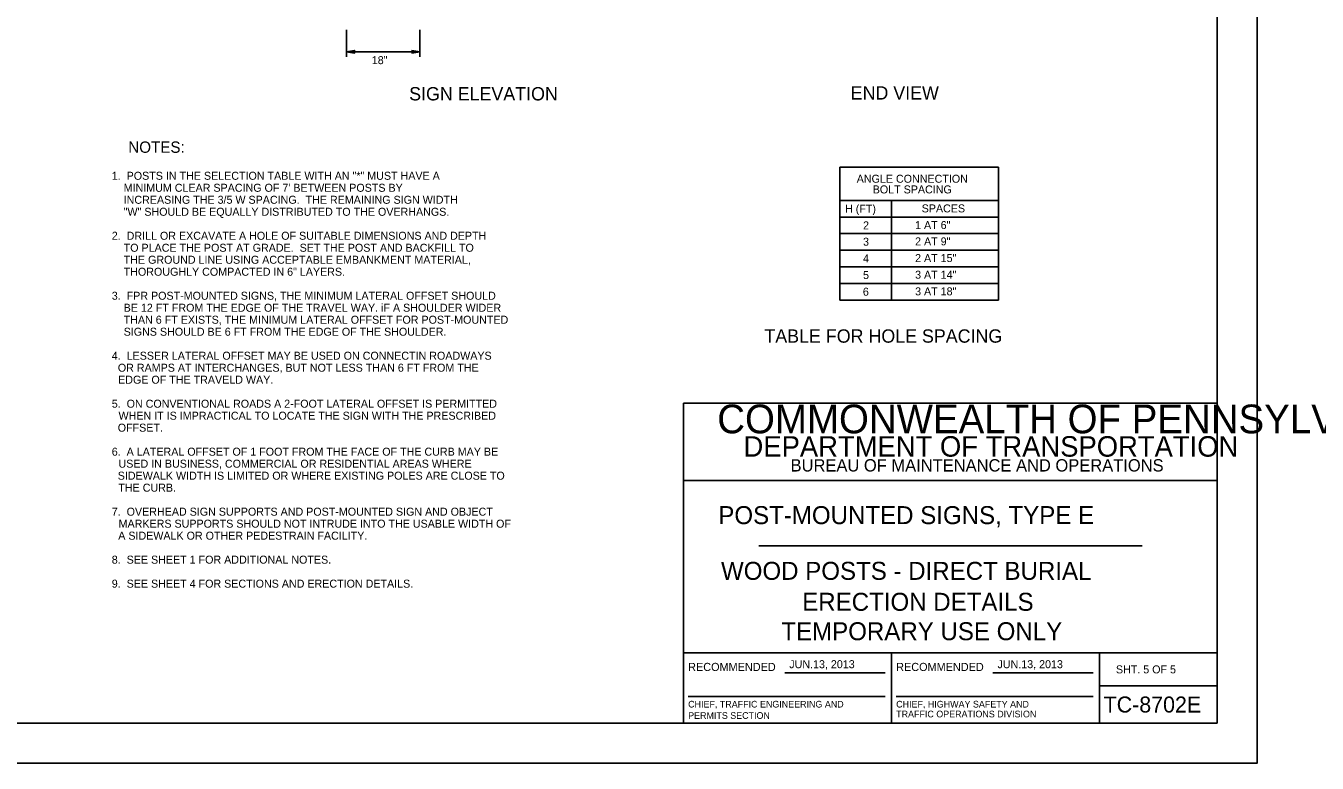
# Model space of a CAD drawing. Extents: x -2340 to 628, y -879 to 309.
# Drawn here: x -738 to -253.8, y -878.6 to -602 of the extents above; entities that cross this region are included whole.
import ezdxf

# ---------------------------------------------------------------- set-up
doc = ezdxf.new("R2010")
doc.units = 0
for name, color, linetype in [('Level 1', 7, 'Continuous'), ('Level 2', 7, 'Continuous'), ('Level 3', 7, 'Continuous'), ('Level 4', 7, 'Continuous'), ('PLT-BNDY', 7, 'Continuous')]:
    doc.layers.add(name, color=color, linetype=linetype)

msp = doc.modelspace()

# ---------------------------------------------------------------- linework, layer by layer
at = {"layer": 'Level 1'}
for p, q in [((-291.39, -863.56), (-291.39, -299.56)), ((-491.39, -863.56), (-491.39, -743.56)), ((-491.39, -743.56), (-291.39, -743.56)), ((-291.39, -772.56), (-491.39, -772.56)), ((-463.14, -797.06), (-319.51, -797.06)), ((-491.39, -837.19), (-291.39, -837.19)), ((-413.39, -837.19), (-413.39, -863.56)), ((-335.51, -863.56), (-335.51, -837.19)), ((-453.45, -844.62), (-415.83, -844.62)), ((-375.45, -844.62), (-337.83, -844.62)), ((-335.51, -849.56), (-291.39, -849.56)), ((-489.7, -853.51), (-415.83, -853.51)), ((-411.7, -853.51), (-337.83, -853.51)), ((-291.39, -863.56), (-1077.39, -863.56)), ((-1077.39, -863.56), (-491.39, -863.56))]:
    msp.add_line(p, q, dxfattribs=at)
at = {"layer": 'Level 2'}
for p, q in [((-373.31, -654.95), (-432.81, -654.95)), ((-432.81, -704.83), (-432.81, -654.95)), ((-373.31, -704.83), (-373.31, -654.95)), ((-373.31, -667.45), (-432.81, -667.45)), ((-413.42, -704.83), (-413.42, -667.45)), ((-373.31, -673.7), (-432.81, -673.7)), ((-373.31, -679.83), (-432.81, -679.83)), ((-373.31, -686.08), (-432.81, -686.08)), ((-373.31, -692.33), (-432.81, -692.33)), ((-373.31, -698.58), (-432.81, -698.58)), ((-373.31, -704.83), (-432.81, -704.83))]:
    msp.add_line(p, q, dxfattribs=at)
at = {"layer": 'Level 3'}
for p, q in [((-617.78, -613.59), (-617.78, -603.47)), ((-590.28, -613.59), (-590.28, -603.47)), ((-617.78, -611.72), (-590.28, -611.72))]:
    msp.add_line(p, q, dxfattribs=at)
for points in [[(-614.78, -612.09), (-614.9, -611.84), (-617.78, -611.72), (-614.78, -612.09), (-614.78, -612.22), (-617.78, -611.72), (-614.9, -611.59), (-614.78, -611.34), (-617.78, -611.72), (-614.78, -611.22), (-614.78, -611.34)], [(-593.15, -611.34), (-593.03, -611.59), (-590.28, -611.72), (-593.15, -611.34), (-593.28, -611.22), (-590.28, -611.72), (-593.03, -611.84), (-593.15, -612.09), (-590.28, -611.72), (-593.28, -612.22), (-593.15, -612.09)]]:
    msp.add_lwpolyline(points, dxfattribs=at)
at = {"layer": 'PLT-BNDY'}
msp.add_lwpolyline([(-1117.39, -284.56), (-276.39, -284.56), (-276.39, -878.56), (-1117.39, -878.56)], close=True, dxfattribs=at)

# ---------------------------------------------------------------- texts
at = {"layer": 'Level 1'}
for s, height, p in [('COMMONWEALTH OF PENNSYLVANIA', 10.7827, (-478.79, -754.83)), ('DEPARTMENT OF TRANSPORTATION', 7.6838, (-468.93, -763.58)), ('BUREAU OF MAINTENANCE AND OPERATIONS', 4.6252, (-451.29, -769.15)), ('POST-MOUNTED SIGNS, TYPE E', 6.7492, (-478.39, -788.89)), ('WOOD POSTS - DIRECT BURIAL', 6.7492, (-477.38, -809.79)), ('ERECTION DETAILS ', 6.7492, (-446.93, -821.4)), ('TEMPORARY USE ONLY', 6.7492, (-454.76, -832.44)), ('RECOMMENDED', 3.048, (-489.7, -843.99)), ('RECOMMENDED', 3.048, (-411.7, -843.99)), ('SHT. 5 OF 5', 3, (-329.3, -844.88)), ('CHIEF, TRAFFIC ENGINEERING AND', 2.5, (-489.7, -857.68)), ('CHIEF, HIGHWAY SAFETY AND', 2.5, (-411.7, -857.68)), ('TC-8702E', 6, (-333.91, -859.56)), ('PERMITS SECTION', 2.5, (-489.7, -861.93)), ('TRAFFIC OPERATIONS DIVISION', 2.5, (-411.7, -861.38))]:
    msp.add_text(s, height=height, dxfattribs=at).set_placement(p)
at = {"layer": 'Level 2'}
for p in [(-451.78, -842.93), (-373.71, -842.93)]:
    msp.add_text('JUN.13, 2013', height=3, dxfattribs=at).set_placement(p)
at = {"layer": 'Level 3'}
for s, height, p in [('18"', 3, (-608.32, -616.35)), ('SIGN ELEVATION', 5, (-594.3, -629.96)), ('END VIEW', 5, (-428.75, -629.63)), ('NOTES:', 4.25, (-699.61, -649.61)), ('ANGLE CONNECTION', 3, (-426.49, -660.83)), ('BOLT SPACING', 3, (-420.49, -664.84)), ('H (FT)', 3, (-430.87, -672.08)), ('SPACES', 3, (-402.14, -671.96)), ('2', 3, (-424.11, -678.33)), ('1 AT 6"', 3, (-404.6, -678.2)), ('3', 3, (-424.12, -684.45)), ('2 AT 9"', 3, (-404.6, -684.33)), ('2 AT 15"', 3, (-404.6, -690.58)), ('4', 3, (-424.11, -690.7)), ('5', 3, (-424.12, -696.95)), ('3 AT 14"', 3, (-404.6, -696.83)), ('6', 3, (-424.19, -703.2)), ('3 AT 18"', 3, (-404.6, -703.08)), ('TABLE FOR HOLE SPACING', 5, (-461.1, -720.83))]:
    msp.add_text(s, height=height, dxfattribs=at).set_placement(p)
at = {"layer": 'Level 4'}
for s, p in [('1.  POSTS IN THE SELECTION TABLE WITH AN "*" MUST HAVE A', (-705.81, -659.72)), ("    MINIMUM CLEAR SPACING OF 7' BETWEEN POSTS BY", (-705.81, -664.22)), ('    INCREASING THE 3/5 W SPACING.  THE REMAINING SIGN WIDTH', (-705.81, -668.72)), ('    "W" SHOULD BE EQUALLY DISTRIBUTED TO THE OVERHANGS.', (-705.81, -673.22)), ('2.  DRILL OR EXCAVATE A HOLE OF SUITABLE DIMENSIONS AND DEPTH', (-705.81, -682.22)), ('    TO PLACE THE POST AT GRADE.  SET THE POST AND BACKFILL TO', (-705.81, -686.72)), ('    THE GROUND LINE USING ACCEPTABLE EMBANKMENT MATERIAL,', (-705.81, -691.22)), ('    THOROUGHLY COMPACTED IN 6" LAYERS.', (-705.81, -695.72)), ('3.  FPR POST-MOUNTED SIGNS, THE MINIMUM LATERAL OFFSET SHOULD ', (-705.81, -704.72)), ('    BE 12 FT FROM THE EDGE OF THE TRAVEL WAY. iF A SHOULDER WIDER ', (-705.81, -709.22)), ('    THAN 6 FT EXISTS, THE MINIMUM LATERAL OFFSET FOR POST-MOUNTED ', (-705.81, -713.72)), ('    SIGNS SHOULD BE 6 FT FROM THE EDGE OF THE SHOULDER.', (-705.81, -718.22)), ('4.  LESSER LATERAL OFFSET MAY BE USED ON CONNECTIN ROADWAYS ', (-705.81, -727.22)), ('     OR RAMPS AT INTERCHANGES, BUT NOT LESS THAN 6 FT FROM THE ', (-709.11, -731.72)), ('     EDGE OF THE TRAVELD WAY.', (-709, -736.22)), ('5.  ON CONVENTIONAL ROADS A 2-FOOT LATERAL OFFSET IS PERMITTED ', (-705.81, -745.22)), ('     WHEN IT IS IMPRACTICAL TO LOCATE THE SIGN WITH THE PRESCRIBED ', (-708.85, -749.72)), ('     OFFSET.', (-709.14, -754.22)), ('6.  A LATERAL OFFSET OF 1 FOOT FROM THE FACE OF THE CURB MAY BE ', (-705.81, -763.22)), ('     USED IN BUSINESS, COMMERCIAL OR RESIDENTIAL AREAS WHERE ', (-708.86, -767.72)), ('     SIDEWALK WIDTH IS LIMITED OR WHERE EXISTING POLES ARE CLOSE TO ', (-709.15, -772.22)), ('     THE CURB.', (-708.92, -776.72)), ('7.  OVERHEAD SIGN SUPPORTS AND POST-MOUNTED SIGN AND OBJECT ', (-705.81, -785.72)), ('     MARKERS SUPPORTS SHOULD NOT INTRUDE INTO THE USABLE WIDTH OF ', (-708.82, -790.22)), ('     A SIDEWALK OR OTHER PEDESTRAIN FACILITY.', (-708.96, -794.72)), ('8.  SEE SHEET 1 FOR ADDITIONAL NOTES.', (-705.81, -803.72)), ('9.  SEE SHEET 4 FOR SECTIONS AND ERECTION DETAILS.', (-705.81, -812.72))]:
    msp.add_text(s, height=3, dxfattribs=at).set_placement(p)

doc.saveas('drawing.dxf')
